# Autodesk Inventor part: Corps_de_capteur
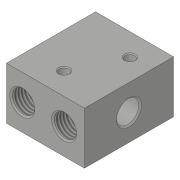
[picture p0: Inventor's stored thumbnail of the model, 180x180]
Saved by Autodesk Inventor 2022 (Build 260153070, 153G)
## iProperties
RuleStatus: InUse
Created: 2018-06
Part Number: Corps_de_capteur
Material: Aluminium 6061
Document SubType Name: Modeling
Designer: Fabian Perrée
Density: 2.7 g/cm^3
Appearance: Gris clair
Mass: 125.414 g
Surface Area: 130.388 cm^2
Volume: 46.4496 cm^3
Author: Fabian Perrée
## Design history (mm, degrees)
sketch "Esquisse1"
  geometry: L1 (-21, 24)-(21, 24); L2 (21, 24)-(21, -24); L3 (21, -24)-(-21, -24); L4 (-21, -24)-(-21, 24); L5 (-21, 24)-(21, -24); L6 (21, 24)-(-21, -24); 1 further point
  constraints: 12 end point, 2 midpoint, 2 parallel, 1 horizontal, 1 perpendicular
  dimensions: "d0" = 48 distance of L1.end L2.end; "d1" = 42 distance of L2.end L3.end
extrude "Extrusion1" new body sketch "Esquisse1" stored distance "d2" = 28; taper "d3" = 0 deg
sketch "Esquisse2"
  geometry: L1 (21, 24)-(21, -24) reference; L2 (21, 0)-(-21, 0); L3 (-21, 24)-(21, 24) reference; L4 (21, -24)-(-21, -24) reference; L5 (0, -24)-(0, 24); L6 (12.5, 24)-(12.5, 0); L7 (18.5, 24)-(18.5, 13); L8 (18.5, 13)-(17.75, 13); L9 (16.25, 11.5)-(16.25, 10); L10 (16.25, 10)-(14.5, 10); L11 (14.5, 10)-(14.5, 0); L12 (21, -6)-(8.5, -6); L13 (8.5, -6)-(8.5, -5.25); L14 (8.5, -5.25)-(5.5, -5.25); L15 (5.5, -5.25)-(5.5, -2.5); L16 (5.5, -2.5)-(0.5, -2.5); L17 (0.5, -2.5)-(0.5, -2); L18 (0.5, -2)-(-0.5, -2); L19 (-0.5, -2)-(-0.5, -6); L20 (-0.5, -6)-(-21, -6); L21 (-21, -24)-(-21, 24) reference; L22 (21, -6)-(21, 0); L23 (-21, -6)-(-21, 0); A1 r 1.5 centre (17.75, 11.5) between (17.75, 13) and (16.25, 11.5); 2 further points
  constraints: 38 end point, 12 perpendicular, 8 point on line, 3 horizontal, 3 midpoint, 2 point on circle, 2 tangent, 1 centre point, 1 collinear, 1 parallel, 1 vertical
  dimensions: "d6" = 12 diameter of L7 L6; "d7" = 8.5 distance between parallel lines of L1 L6; "d8" = 7.5 diameter of L9 L6; "d9" = 4 diameter of L11 L6; "d10" = 11 distance of L7.start L7.end; "d11" = 3 distance of point (16.25, 13) L9.end; "d12" = 1.5 radius of A1; "d19" = 12 diameter of L12 L2; "d20" = 10.5 diameter of L14 L2; "d21" = 5 diameter of L16 L2; "d22" = 4 diameter of L18 L2; "d23" = 1 distance of L17.end L18.end; "d24" = 12 diameter of L20 L2; "d25" = 12.5 distance of L12.start L12.end; "d26" = 15.5 distance between parallel lines of L15 L1; "d27" = 20.5 distance of L19.end L20.end
revolve "Révolution1" stored, may be unused: angle "d35" = 90 deg
sketch "Esquisse3"
  geometry: C1 r 6 at (8.5, -14) reference; 2 further points
  constraints: 1 horizontal alignment
  dimensions: "d36" = 22.5 distance of C1.centre point (31, -14)
sketch "Esquisse4"
  geometry: L1 (42, 0)-(42, -28) reference; 2 further points
  constraints: 1 horizontal alignment
  dimensions: "d37" = 18 distance from line of L1 point (24, -14)
feature "Filetage1" dims "d42" = 10, "d43" = 0
feature "Réseau basé sur une esquisse1"
feature "Réseau basé sur une esquisse2"
revolve "Révolution2" stored, may be unused: angle "d38" = 90 deg
feature "Filetage2" dims "d47" = 10, "d48" = 0
sketch "Esquisse5"
  geometry: C1 r 2.5 at (-24, 14) reference; C2 r 2 at (-24, 14) reference; 2 further points
  dimensions: "d49" = 19 horizontal distance of C1.centre point (-43, 5); "d50" = 9 vertical distance of C2.centre point (-43, 5); "d51" = 19 horizontal distance of point (-5, 23) C1.centre; "d52" = 9 vertical distance of point (-5, 23) C1.centre
hole "Perçage1" sketch "Esquisse5" at (-43, 5), (-5, 23) diameter "d53" = 4.134; stored, may be unused: countersink angle "d57" = 90 deg, drill point angle "d59" = 118 deg; dims "d54" = 10, "d55" = 4, "d56" = 2, "d58" = 12.5
sketch "Esquisse6"
  geometry: L1 (21, 24)-(-21, 24) reference; L2 (21, -24)-(21, 24) reference; L3 (-21, 24)-(-21, -24) reference; L4 (-21, -24)-(21, -24) reference; 3 further points
  dimensions: "d63" = 12 distance from line of L1 point (9.5, 12); "d65" = 19 distance from line of L3 point (-2, -12); "d66" = 12 distance from line of L4 point (-2, -12); "d74" = 30.5 distance from line of L3 point (9.5, 12)
hole "Perçage2" sketch "Esquisse6" at (9.5, 12), (-2, -12) diameter "d67" = 5; stored, may be unused: countersink angle "d71" = 90 deg, drill point angle "d73" = 118 deg; dims "d68" = 10, "d69" = 6, "d70" = 2, "d72" = 12.5
chamfer "Chanfrein4" distance "d75" = 0.75; stored, may be unused: second distance "d76" = 2, angle "d77" = 45 deg
node "Solide1"
